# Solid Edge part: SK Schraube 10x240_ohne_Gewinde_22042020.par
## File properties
Author: fknapp
Template: Normal.par
Last saved by: fknapp
Revision: 26
Application: Solid Edge
Username: fknapp
Material: Aluminium
Genauigkeit: 0,99
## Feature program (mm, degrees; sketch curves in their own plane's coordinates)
sketch for "unnamed RevolvedProtrusion 1" plane through (0, 0, 0) normal (0, 0, 1) x-axis (1, 0, 0)
  line (0, 54) -> (9, 54)
  line (9, 54) -> (9, 53)
  line (9, 53) -> (5, 49)
  line (5, 49) -> (5, 46.3)
  line (5, 46.3) -> (4.7548, 46.3)
  arc centre (4.7548, 44.6952) radius 1.6048 from (4.7548, 46.3) to (3.15, 44.6952) ccw
  line (3.15, 44.6952) -> (3.15, 42)
  line (3.15, 42) -> (5, 42)
  line (5, -173) -> (5, 42)
  line (0.5, -186) -> (5, -173)
  line (0, -186) -> (0.5, -186)
revolve "unnamed RevolvedProtrusion 1" add full turn 360 deg about sketch line (0, 54) -> (0, -186)
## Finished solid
Body 1: solid body, 11 faces, 10 edges, 0 vertices.
  Faces by surface: cylinder 4, plane 4, cone 2, torus 1
  Edges by curve: circle 10
Bounding box of the edges (mm; curved faces can reach further): 18.000 x 240.000 x 18.000, from (-9, -186, -9) to (9, 54, 9).
Cylindrical faces by radius (mm): R3.15 x1, R5 x2, R9 x1
Conical faces (half-angle, radius in mm at the cone's reference point): 19.0935 deg R5 x1, 45 deg R9 x1
Toroidal faces (ring radius, tube radius in mm): R4.7548 r1.6048 x1
Planar faces by outward normal: +y 2, -y 2
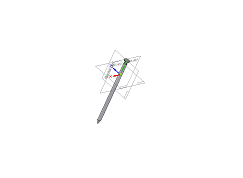
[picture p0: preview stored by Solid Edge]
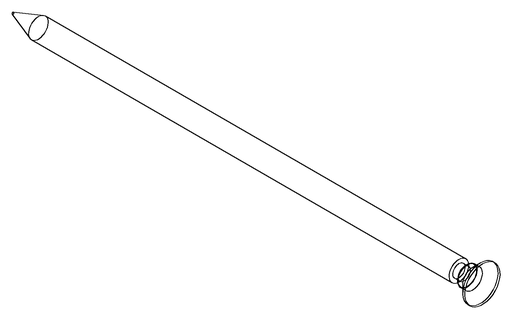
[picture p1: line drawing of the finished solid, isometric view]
